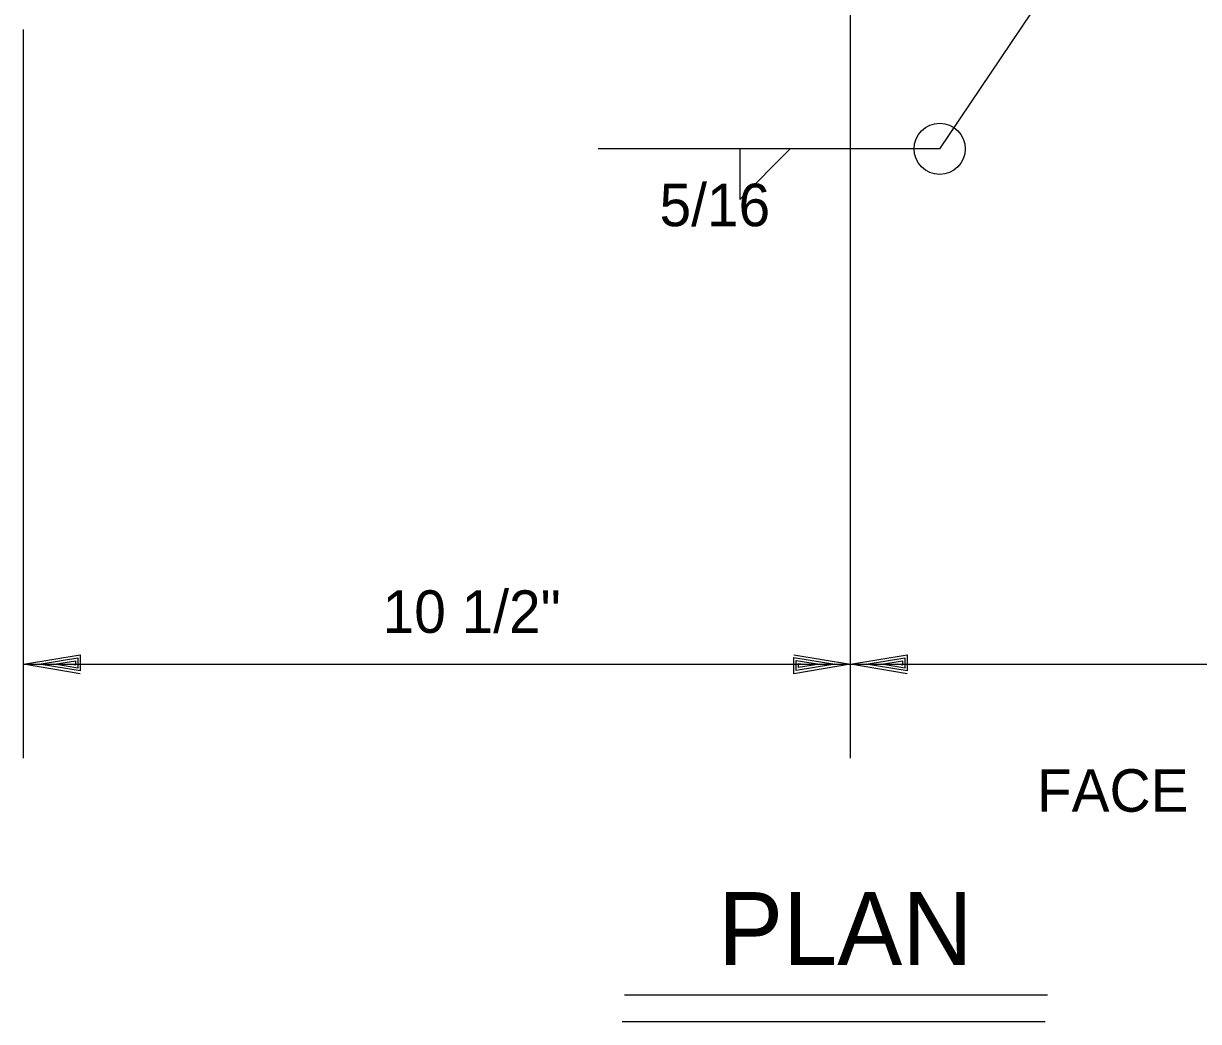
# Model space of a CAD drawing. Extents: x 0.1 to 13.5, y 0.1 to 9.5.
# Drawn here: x 2.648 to 3.938, y 4.266 to 5.362 of the extents above; entities that cross this region are included whole.
import ezdxf

# ---------------------------------------------------------------- set-up
doc = ezdxf.new("R2010")
doc.units = 0
for name, color, linetype in [('Level 2', 7, 'Continuous'), ('Level 25', 7, 'Continuous'), ('Level 3', 7, 'Continuous'), ('Level 50', 7, 'Continuous')]:
    doc.layers.add(name, color=color, linetype=linetype)

msp = doc.modelspace()

# ---------------------------------------------------------------- linework, layer by layer
at = {"layer": 'Level 2'}
msp.add_line((3.556, 4.5548), (3.556, 6.7297), dxfattribs=at)
at = {"layer": 'Level 25'}
for p, q in [((3.654, 5.2243), (4.1729, 5.9943)), ((2.6479, 4.5548), (2.6479, 5.3552)), ((3.654, 5.2243), (3.2789, 5.2243)), ((3.4344, 5.2249), (3.4344, 5.1686)), ((3.4344, 5.1686), (3.4902, 5.2245)), ((2.6479, 4.6581), (3.556, 4.6581)), ((3.556, 4.6581), (4.4935, 4.6581)), ((3.3079, 4.295), (3.7725, 4.295)), ((3.3052, 4.2656), (3.7698, 4.2656))]:
    msp.add_line(p, q, dxfattribs=at)
msp.add_circle((3.654, 5.2243), 0.0281, dxfattribs=at)
at = {"layer": 'Level 50'}
for p, q in [((2.6479, 4.6581), (2.6479, 4.6581)), ((2.6653, 4.6581), (2.6653, 4.6581)), ((3.5387, 4.6581), (3.5387, 4.6581)), ((3.556, 4.6581), (3.556, 4.6581)), ((3.556, 4.6581), (3.556, 4.6581)), ((3.5734, 4.6581), (3.5734, 4.6581))]:
    msp.add_line(p, q, dxfattribs=at)
for points in [[(2.7103, 4.6477), (2.6479, 4.6581), (2.7103, 4.6684), (2.7103, 4.6507), (2.6653, 4.6581), (2.7076, 4.6651), (2.7076, 4.6537), (2.6819, 4.6581), (2.7049, 4.6617), (2.7049, 4.6571), (2.6993, 4.6581)], [(3.4937, 4.6684), (3.556, 4.6581), (3.4937, 4.6477), (3.4937, 4.6654), (3.5387, 4.6581), (3.4964, 4.6511), (3.4964, 4.6624), (3.522, 4.6581), (3.499, 4.6544), (3.499, 4.6591), (3.5047, 4.6581)], [(3.6184, 4.6477), (3.556, 4.6581), (3.6184, 4.6684), (3.6184, 4.6507), (3.5734, 4.6581), (3.6157, 4.6651), (3.6157, 4.6537), (3.59, 4.6581), (3.613, 4.6617), (3.613, 4.6571), (3.6074, 4.6581)]]:
    msp.add_lwpolyline(points, dxfattribs=at)

# ---------------------------------------------------------------- texts
at = {"layer": 'Level 3'}
for s, height, p in [('5/16', 0.04667, (3.3464, 5.1393)), ('10 1/2"', 0.04667, (3.0423, 4.6926)), ('FACE OF WALL', 0.046667, (3.7608, 4.4961)), ('PLAN', 0.08, (3.4107, 4.3278))]:
    msp.add_text(s, height=height, dxfattribs=at).set_placement(p)

doc.saveas('drawing.dxf')
